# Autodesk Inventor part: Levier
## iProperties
Author: Flavien MARTY
Shininess: 60.0
PropertySet Name: _Private Model Information
Created: 2001-10
Part Number: Levier
Material: Par défaut
Document SubType Name: Modélisation
Designer: Flavien MARTY
Control State: 0
Master: False
Checked Out: False
PropertySet Name: Design Tracking Control
Density: 0.0
Volumn: 0.0
Area: 0.0
PropertySet Name: Model Information
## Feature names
1. Base1
